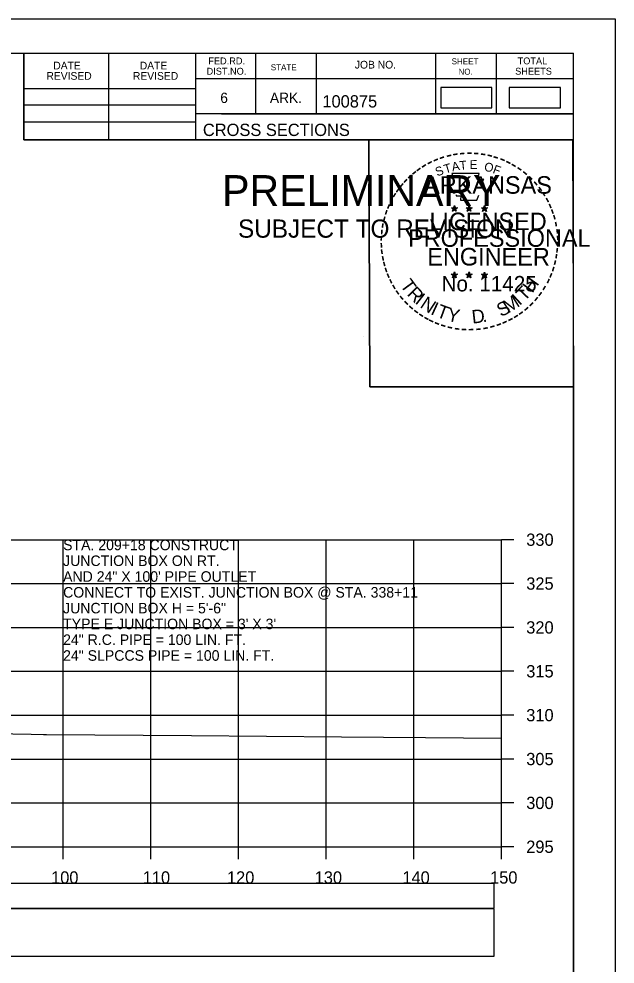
# Model space of a CAD drawing. Extents: x 1368122 to 1710785, y 373130 to 557566.
# Drawn here: x 1370117.2 to 1370185.2, y 374942.6 to 375050.4 of the extents above; entities that cross this region are included whole.
import ezdxf

# ---------------------------------------------------------------- set-up
doc = ezdxf.new("R2010")
doc.units = 0
for name, color, linetype in [('R_Axis', 7, 'Continuous'), ('R_Axis Annot', 7, 'Continuous'), ('R_Border', 7, 'Continuous'), ('R_Border PE', 7, 'Continuous'), ('R_Border Prem', 7, 'Continuous'), ('R_Drive', 7, 'Continuous'), ('R_Exist Surface', 7, 'Continuous'), ('R_Grid', 7, 'Continuous'), ('R_No Plot', 7, 'Continuous'), ('R_Water Annot', 7, 'Continuous')]:
    doc.layers.add(name, color=color, linetype=linetype)

msp = doc.modelspace()

# ---------------------------------------------------------------- linework, layer by layer
for points in [[(1369873.09, 374949), (1370171.39, 374949), (1370171.39, 374951.82), (1369873.09, 374951.82)], [(1369873.09, 374943.54), (1370171.39, 374943.54), (1370171.39, 374948.95), (1369873.09, 374948.95)]]:
    msp.add_lwpolyline(points, close=True)
at = {"layer": 'R_Axis'}
for p, q in [((1370172.24, 374956.01), (1370172.24, 374991.01)), ((1370173.64, 374991.01), (1370172.24, 374991.01)), ((1370173.64, 374986.01), (1370172.24, 374986.01)), ((1370173.64, 374981.01), (1370172.24, 374981.01)), ((1370173.64, 374976.01), (1370172.24, 374976.01)), ((1370173.64, 374971.01), (1370172.24, 374971.01)), ((1370173.64, 374966.01), (1370172.24, 374966.01)), ((1370173.64, 374961.01), (1370172.24, 374961.01)), ((1369872.24, 374956.01), (1370172.24, 374956.01)), ((1370122.24, 374954.61), (1370122.24, 374956.01)), ((1370132.24, 374954.61), (1370132.24, 374956.01)), ((1370142.24, 374954.61), (1370142.24, 374956.01)), ((1370152.24, 374954.61), (1370152.24, 374956.01)), ((1370162.24, 374954.61), (1370162.24, 374956.01)), ((1370172.24, 374954.61), (1370172.24, 374956.01)), ((1370173.64, 374956.01), (1370172.24, 374956.01))]:
    msp.add_line(p, q, dxfattribs=at)
at = {"layer": 'R_Border'}
for p, q in [((1369864.24, 375046.47), (1370180.42, 375046.47)), ((1370117.78, 375036.59), (1370117.78, 375046.47)), ((1370127.46, 375036.59), (1370127.46, 375046.47)), ((1370137.32, 375046.47), (1370137.32, 375036.59)), ((1370144.16, 375046.47), (1370144.16, 375039.53)), ((1370151.1, 375046.47), (1370151.1, 375039.53)), ((1370164.68, 375046.47), (1370164.68, 375039.53)), ((1370171.62, 375046.47), (1370171.62, 375039.53)), ((1370180.42, 374841.01), (1370180.42, 375046.47)), ((1370180.42, 375043.53), (1370137.32, 375043.53)), ((1370180.42, 375043.55), (1370180.42, 375043.55)), ((1370117.78, 375042.45), (1370137.32, 375042.45)), ((1370117.78, 375040.59), (1370137.32, 375040.59)), ((1370180.42, 375039.53), (1370137.32, 375039.53)), ((1370140.28, 375039.53), (1370180.42, 375039.53)), ((1370117.78, 375038.65), (1370137.32, 375038.65)), ((1370180.42, 375036.59), (1370117.78, 375036.59))]:
    msp.add_line(p, q, dxfattribs=at)
at = {"layer": 'R_Border PE'}
for p, q in [((1370166.51, 375028.85), (1370166.85, 375028.74)), ((1370166.51, 375028.85), (1370166.76, 375028.8)), ((1370166.51, 375028.85), (1370166.74, 375028.73)), ((1370166.64, 375028.44), (1370166.85, 375028.74)), ((1370166.64, 375028.44), (1370166.76, 375028.68)), ((1370166.64, 375028.44), (1370166.85, 375028.66)), ((1370166.85, 375029.1), (1370166.81, 375028.85)), ((1370166.85, 375028.74), (1370166.85, 375029.1)), ((1370166.85, 375029.1), (1370166.9, 375028.85)), ((1370167.2, 375028.85), (1370166.85, 375028.74)), ((1370167.07, 375028.44), (1370166.85, 375028.74)), ((1370167.07, 375028.44), (1370166.85, 375028.65)), ((1370167.2, 375028.85), (1370166.92, 375028.8)), ((1370167.07, 375028.44), (1370166.93, 375028.73)), ((1370167.2, 375028.85), (1370167, 375028.75)), ((1370168.18, 375028.85), (1370168.52, 375028.74)), ((1370168.18, 375028.85), (1370168.43, 375028.8)), ((1370168.18, 375028.85), (1370168.41, 375028.73)), ((1370168.31, 375028.44), (1370168.52, 375028.74)), ((1370168.31, 375028.44), (1370168.43, 375028.68)), ((1370168.31, 375028.44), (1370168.52, 375028.66)), ((1370168.52, 375029.1), (1370168.48, 375028.85)), ((1370168.52, 375028.74), (1370168.52, 375029.1)), ((1370168.52, 375029.1), (1370168.57, 375028.85)), ((1370168.87, 375028.85), (1370168.52, 375028.74)), ((1370168.74, 375028.44), (1370168.52, 375028.74)), ((1370168.74, 375028.44), (1370168.52, 375028.65)), ((1370168.87, 375028.85), (1370168.59, 375028.8)), ((1370168.74, 375028.44), (1370168.6, 375028.73)), ((1370168.87, 375028.85), (1370168.67, 375028.75)), ((1370169.94, 375028.84), (1370170.29, 375028.73)), ((1370169.94, 375028.84), (1370170.19, 375028.79)), ((1370169.94, 375028.84), (1370170.18, 375028.71)), ((1370170.07, 375028.43), (1370170.29, 375028.73)), ((1370170.07, 375028.43), (1370170.2, 375028.67)), ((1370170.07, 375028.43), (1370170.29, 375028.65)), ((1370170.29, 375029.09), (1370170.25, 375028.84)), ((1370170.29, 375028.73), (1370170.29, 375029.09)), ((1370170.29, 375029.09), (1370170.34, 375028.84)), ((1370170.64, 375028.84), (1370170.29, 375028.73)), ((1370170.5, 375028.43), (1370170.29, 375028.73)), ((1370170.5, 375028.43), (1370170.29, 375028.64)), ((1370170.64, 375028.84), (1370170.35, 375028.79)), ((1370170.5, 375028.43), (1370170.36, 375028.72)), ((1370170.64, 375028.84), (1370170.43, 375028.73)), ((1370166.5, 375021.28), (1370166.85, 375021.16)), ((1370166.5, 375021.28), (1370166.75, 375021.23)), ((1370166.5, 375021.28), (1370166.74, 375021.15)), ((1370166.63, 375020.87), (1370166.85, 375021.16)), ((1370166.63, 375020.87), (1370166.76, 375021.11)), ((1370166.63, 375020.87), (1370166.85, 375021.08)), ((1370166.85, 375021.53), (1370166.81, 375021.28)), ((1370166.85, 375021.16), (1370166.85, 375021.53)), ((1370166.85, 375021.53), (1370166.9, 375021.28)), ((1370167.2, 375021.28), (1370166.85, 375021.16)), ((1370167.06, 375020.87), (1370166.85, 375021.16)), ((1370167.06, 375020.87), (1370166.85, 375021.08)), ((1370167.2, 375021.28), (1370166.91, 375021.23)), ((1370167.06, 375020.87), (1370166.93, 375021.16)), ((1370167.2, 375021.28), (1370166.99, 375021.17)), ((1370168.17, 375021.28), (1370168.52, 375021.16)), ((1370168.17, 375021.28), (1370168.42, 375021.23)), ((1370168.17, 375021.28), (1370168.41, 375021.15)), ((1370168.3, 375020.87), (1370168.52, 375021.16)), ((1370168.3, 375020.87), (1370168.43, 375021.11)), ((1370168.3, 375020.87), (1370168.52, 375021.08)), ((1370168.52, 375021.53), (1370168.48, 375021.28)), ((1370168.52, 375021.16), (1370168.52, 375021.53)), ((1370168.52, 375021.53), (1370168.57, 375021.28)), ((1370168.87, 375021.28), (1370168.52, 375021.16)), ((1370168.73, 375020.87), (1370168.52, 375021.16)), ((1370168.73, 375020.87), (1370168.52, 375021.08)), ((1370168.87, 375021.28), (1370168.58, 375021.23)), ((1370168.73, 375020.87), (1370168.6, 375021.16)), ((1370168.87, 375021.28), (1370168.66, 375021.17)), ((1370169.94, 375021.27), (1370170.29, 375021.15)), ((1370169.94, 375021.27), (1370170.19, 375021.22)), ((1370169.94, 375021.27), (1370170.17, 375021.14)), ((1370170.07, 375020.86), (1370170.29, 375021.15)), ((1370170.07, 375020.86), (1370170.2, 375021.1)), ((1370170.07, 375020.86), (1370170.28, 375021.07)), ((1370170.29, 375021.52), (1370170.25, 375021.27)), ((1370170.5, 375020.86), (1370170.28, 375021.07)), ((1370170.29, 375021.15), (1370170.29, 375021.52)), ((1370170.29, 375021.52), (1370170.34, 375021.27)), ((1370170.63, 375021.27), (1370170.29, 375021.15)), ((1370170.5, 375020.86), (1370170.29, 375021.15)), ((1370170.63, 375021.27), (1370170.35, 375021.22)), ((1370170.5, 375020.86), (1370170.36, 375021.15)), ((1370170.63, 375021.27), (1370170.43, 375021.16))]:
    msp.add_line(p, q, dxfattribs=at)
for points in [[(1370166.55, 375032.73), (1370166.82, 375031.9)], [(1370170.06, 375031.8), (1370170.2, 375032.09), (1370169.51, 375032.06), (1370169.66, 375032.73), (1370166.55, 375032.73)], [(1370167.04, 375030.3), (1370167.04, 375030.22), (1370167.6, 375030.2), (1370167.55, 375029.72), (1370169.42, 375029.72), (1370169.62, 375030.26)], [(1370166.85, 375029.1), (1370167.07, 375028.44), (1370166.51, 375028.85), (1370167.2, 375028.85), (1370166.64, 375028.44), (1370166.85, 375029.1)], [(1370168.52, 375029.1), (1370168.74, 375028.44), (1370168.18, 375028.85), (1370168.87, 375028.85), (1370168.31, 375028.44), (1370168.52, 375029.1)], [(1370170.29, 375029.09), (1370170.5, 375028.43), (1370169.94, 375028.84), (1370170.64, 375028.84), (1370170.07, 375028.43), (1370170.29, 375029.09)], [(1370166.85, 375021.53), (1370167.06, 375020.87), (1370166.5, 375021.28), (1370167.2, 375021.28), (1370166.63, 375020.87), (1370166.85, 375021.53)], [(1370168.52, 375021.53), (1370168.73, 375020.87), (1370168.17, 375021.28), (1370168.87, 375021.28), (1370168.3, 375020.87), (1370168.52, 375021.53)], [(1370170.29, 375021.52), (1370170.5, 375020.86), (1370169.94, 375021.27), (1370170.63, 375021.27), (1370170.07, 375020.86), (1370170.29, 375021.52)]]:
    msp.add_lwpolyline(points, dxfattribs=at)
for centre, radius in [((1370166.85, 375028.74), 0.172), ((1370166.85, 375028.74), 0.145), ((1370166.85, 375028.74), 0.116), ((1370166.85, 375028.74), 0.0991), ((1370166.85, 375028.74), 0.0747), ((1370166.85, 375028.74), 0.0495), ((1370166.85, 375028.74), 0.0296), ((1370168.52, 375028.74), 0.172), ((1370168.52, 375028.74), 0.145), ((1370168.52, 375028.74), 0.116), ((1370168.52, 375028.74), 0.0991), ((1370168.52, 375028.74), 0.0747), ((1370168.52, 375028.74), 0.0495), ((1370168.52, 375028.74), 0.0296), ((1370170.29, 375028.72), 0.172), ((1370170.29, 375028.72), 0.145), ((1370170.29, 375028.72), 0.116), ((1370170.29, 375028.72), 0.0991), ((1370170.29, 375028.72), 0.0747), ((1370170.29, 375028.72), 0.0495), ((1370170.29, 375028.72), 0.0296), ((1370166.85, 375021.16), 0.172), ((1370166.85, 375021.16), 0.145), ((1370166.85, 375021.16), 0.116), ((1370166.85, 375021.16), 0.0991), ((1370166.85, 375021.16), 0.0747), ((1370166.85, 375021.16), 0.0495), ((1370166.85, 375021.16), 0.0296), ((1370168.52, 375021.16), 0.172), ((1370168.52, 375021.16), 0.145), ((1370168.52, 375021.16), 0.116), ((1370168.52, 375021.16), 0.0991), ((1370168.52, 375021.16), 0.0747), ((1370168.52, 375021.16), 0.0495), ((1370168.52, 375021.16), 0.0296), ((1370170.29, 375021.15), 0.172), ((1370170.29, 375021.15), 0.145), ((1370170.29, 375021.15), 0.116), ((1370170.29, 375021.15), 0.0991), ((1370170.29, 375021.15), 0.0747), ((1370170.29, 375021.15), 0.0495), ((1370170.29, 375021.15), 0.0296)]:
    msp.add_circle(centre, radius, dxfattribs=at)
at = {"layer": 'R_Drive'}
for points in [[(1370165.29, 375040.25), (1370171.13, 375040.25), (1370171.13, 375042.56), (1370165.29, 375042.56)], [(1370173.1, 375040.25), (1370178.94, 375040.25), (1370178.94, 375042.56), (1370173.1, 375042.56)]]:
    msp.add_lwpolyline(points, close=True, dxfattribs=at)
at = {"layer": 'R_Exist Surface'}
msp.add_lwpolyline([(1370066.84, 374970.53), (1370074.01, 374970.13), (1370083.2, 374969.84), (1370085.11, 374969.76), (1370089.62, 374969.69), (1370092.69, 374969.65), (1370093.81, 374969.62), (1370095.6, 374969.58), (1370103.81, 374969.35), (1370113.73, 374969.01), (1370116.49, 374968.89), (1370118.6, 374968.84), (1370120.02, 374968.82), (1370120.34, 374968.81), (1370136.86, 374968.68), (1370153.98, 374968.54), (1370163.55, 374968.47), (1370172.24, 374968.4)], dxfattribs=at)
at = {"layer": 'R_Grid'}
for p, q in [((1369872.24, 374991.01), (1370172.24, 374991.01)), ((1370122.24, 374956.01), (1370122.24, 374991.01)), ((1370132.24, 374956.01), (1370132.24, 374991.01)), ((1370142.24, 374956.01), (1370142.24, 374991.01)), ((1370152.24, 374956.01), (1370152.24, 374991.01)), ((1370162.24, 374956.01), (1370162.24, 374991.01)), ((1370172.24, 374956.01), (1370172.24, 374991.01)), ((1369872.24, 374986.01), (1370172.24, 374986.01)), ((1369872.24, 374981.01), (1370172.24, 374981.01)), ((1369872.24, 374976.01), (1370172.24, 374976.01)), ((1369872.24, 374971.01), (1370172.24, 374971.01)), ((1369872.24, 374966.01), (1370172.24, 374966.01)), ((1369872.24, 374961.01), (1370172.24, 374961.01)), ((1369872.24, 374956.01), (1370172.24, 374956.01))]:
    msp.add_line(p, q, dxfattribs=at)
at = {"layer": 'R_No Plot'}
for p, q in [((1369851.84, 375050.37), (1370185.17, 375050.37)), ((1370156.45, 375014.14), (1370156.45, 375014.14))]:
    msp.add_line(p, q, dxfattribs=at)
for points in [[(1369851.83, 375050.37), (1370185.17, 375050.37), (1370185.17, 374837.03), (1369851.83, 374837.03)], [(1370098.16, 375046.47), (1370117.78, 375046.47), (1370117.78, 375036.59), (1370133.89, 375036.59), (1370157.09, 375036.59), (1370157.21, 375008.44), (1370180.42, 375008.44), (1370180.42, 374841.01), (1369864.24, 374841.01), (1369864.24, 375046.47)], [(1370157.09, 375036.59), (1370180.3, 375036.59), (1370180.42, 375008.44), (1370157.21, 375008.44)]]:
    msp.add_lwpolyline(points, close=True, dxfattribs=at)

# ---------------------------------------------------------------- texts
at = {"layer": 'R_Axis Annot'}
for s, p in [('330', (1370175.04, 374990.31)), ('325', (1370175.04, 374985.31)), ('320', (1370175.04, 374980.31)), ('315', (1370175.04, 374975.31)), ('310', (1370175.04, 374970.31)), ('305', (1370175.04, 374965.31)), ('300', (1370175.04, 374960.31)), ('295', (1370175.04, 374955.31)), ('100', (1370120.87, 374951.81)), ('110', (1370131.32, 374951.81)), ('120', (1370140.92, 374951.81)), ('130', (1370150.92, 374951.81)), ('140', (1370160.92, 374951.81)), ('150', (1370170.92, 374951.81))]:
    msp.add_text(s, height=1.4, dxfattribs=at).set_placement(p)
at = {"layer": 'R_Border'}
for s, height, p in [('FED.RD.', 0.782, (1370138.8, 375045.19)), ('JOB NO.', 0.879, (1370155.5, 375044.71)), ('SHEET', 0.684, (1370166.54, 375045.19)), ('TOTAL', 0.782, (1370174.06, 375045.19)), ('DATE', 0.879, (1370121.12, 375044.61)), ('DATE', 0.879, (1370130.98, 375044.61)), ('DIST.NO.', 0.782, (1370138.6, 375044.01)), ('STATE', 0.684, (1370145.92, 375044.51)), ('NO.', 0.684, (1370167.32, 375044.01)), ('SHEETS', 0.782, (1370173.78, 375044.01)), ('REVISED', 0.879, (1370120.34, 375043.43)), ('REVISED', 0.879, (1370130.2, 375043.43)), ('6', 1.17, (1370140.16, 375040.79)), ('ARK.', 1.172, (1370145.82, 375040.79)), ('100875', 1.4, (1370151.8, 375040.27)), ('CROSS SECTIONS', 1.4, (1370138.18, 375037.02))]:
    msp.add_text(s, height=height, rotation=360, dxfattribs=at).set_placement(p)
at = {"layer": 'R_Border PE'}
for s, height, rotation, p in [('-', 1.6, 13.6301, (1370166.04, 375034.09)), ('-', 1.6, 10.2193, (1370166.72, 375034.26)), ('-', 1.6, 5.8968, (1370167.45, 375034.37)), ('-', 1.6, 0.1862, (1370168.22, 375034.44)), ('-', 1.6, 357.743, (1370168.95, 375034.43)), ('-', 1.6, 352.1617, (1370169.69, 375034.37)), ('-', 1.6, 347.2049, (1370170.41, 375034.26)), ('-', 1.6, 34.0636, (1370163.43, 375032.9)), ('-', 1.6, 28.7918, (1370164.03, 375033.27)), ('-', 1.6, 24.3072, (1370164.66, 375033.58)), ('-', 1.6, 19.1761, (1370165.29, 375033.85)), ('T', 1, 16.4036, (1370165.82, 375032.74)), ('A', 1, 11.2132, (1370166.64, 375032.99)), ('T', 1, 6.0228, (1370167.49, 375033.15)), ('E', 1, 0.8323, (1370168.6, 375033.26)), ('O', 1, 350.4515, (1370170.2, 375033.05)), ('F', 1, 340.0707, (1370171.15, 375032.82)), ('-', 1.6, 342.3362, (1370171.04, 375034.1)), ('-', 1.6, 337.8551, (1370171.78, 375033.88)), ('-', 1.6, 334.1211, (1370172.41, 375033.61)), ('-', 1.6, 329.6409, (1370172.99, 375033.32)), ('-', 1.6, 42.9622, (1370161.94, 375031.71)), ('-', 1.6, 38.9507, (1370162.38, 375032.12)), ('-', 1.6, 36.2317, (1370162.85, 375032.5)), ('S', 1, 21.594, (1370164.9, 375032.4)), ('-', 1.6, 325.8627, (1370173.63, 375032.96)), ('-', 1.6, 320.5297, (1370174.24, 375032.54)), ('-', 1.6, 50.6142, (1370161.09, 375030.74)), ('-', 1.6, 48.423, (1370161.5, 375031.23)), ('ARKANSAS', 2, 360, (1370163.4, 375030.44)), ('-', 1.6, 315.5786, (1370174.84, 375032.05)), ('-', 1.6, 309.8797, (1370175.41, 375031.5)), ('-', 1.6, 58.0706, (1370160.35, 375029.65)), ('-', 1.6, 54.2325, (1370160.68, 375030.18)), ('-', 1.6, 306.6522, (1370175.94, 375030.9)), ('-', 1.4, 303.6753, (1370176.42, 375030.33)), ('-', 1.6, 62.8713, (1370160.04, 375029.04)), ('-', 1.6, 299.6684, (1370176.74, 375029.72)), ('-', 1.6, 72.3945, (1370159.56, 375027.79)), ('-', 1.6, 67.7743, (1370159.78, 375028.42)), ('DWB', 0.01, 360, (1370166.84, 375028.73)), ('DWB', 0.01, 360, (1370168.51, 375028.73)), ('DWB', 0.01, 360, (1370170.28, 375028.72)), ('-', 1.6, 294.6628, (1370177.06, 375029.11)), ('-', 1.6, 290.5728, (1370177.32, 375028.53)), ('-', 1.6, 75.461, (1370159.37, 375027.08)), ('LICENSED', 2, 360, (1370164, 375026.29)), ('-', 1.6, 285.1233, (1370177.56, 375027.95)), ('-', 1.6, 85.1863, (1370159.16, 375025.68)), ('-', 1.6, 81.2013, (1370159.23, 375026.37)), ('PROFESSIONAL', 2, 360, (1370161.57, 375024.39)), ('-', 1.6, 280.5493, (1370177.76, 375027.21)), ('-', 1.6, 276.5962, (1370177.92, 375026.44)), ('-', 1.6, 89.0622, (1370159.13, 375024.98)), ('-', 1.6, 274.3301, (1370177.98, 375025.72)), ('-', 1.6, 94.1959, (1370159.17, 375024.25)), ('-', 1.6, 98.9479, (1370159.24, 375023.58)), ('ENGINEER', 2, 360, (1370163.76, 375022.26)), ('-', 1.6, 263.5172, (1370177.99, 375024.42)), ('-', 1.6, 269.9407, (1370178.01, 375025.09)), ('-', 1.6, 101.7149, (1370159.38, 375022.85)), ('-', 1.6, 260.9953, (1370177.92, 375023.77)), ('-', 1.6, 105.4578, (1370159.54, 375022.26)), ('-', 1.6, 109.0874, (1370159.75, 375021.62)), ('-', 1.6, 252.8681, (1370177.63, 375022.37)), ('-', 1.6, 255.7626, (1370177.81, 375023.09)), ('-', 1.6, 114.0643, (1370160.01, 375021.03)), ('T', 1.54, 306.0406, (1370160.61, 375020)), ('No. 11425', 1.757, 360, (1370165.39, 375019.31)), ('DWB', 0.01, 360, (1370166.84, 375021.16)), ('DWB', 0.01, 360, (1370168.51, 375021.16)), ('DWB', 0.01, 360, (1370170.27, 375021.15)), ('H', 1.54, 54.6088, (1370175.73, 375019.04)), ('-', 1.6, 247.8887, (1370177.41, 375021.7)), ('-', 1.6, 115.7289, (1370160.31, 375020.41)), ('-', 1.6, 120.4471, (1370160.67, 375019.82)), ('R', 1.54, 314.005, (1370161.37, 375018.95)), ('T', 1.54, 46.6444, (1370174.84, 375018.1)), ('-', 1.6, 239.0712, (1370176.75, 375020.32)), ('-', 1.6, 244.6197, (1370177.15, 375021.07)), ('-', 1.6, 125.8934, (1370161.07, 375019.26)), ('-', 1.6, 130.7181, (1370161.53, 375018.71)), ('I', 1.54, 321.9694, (1370162.27, 375018.02)), ('N', 1.54, 326.5002, (1370162.84, 375017.55)), ('M', 1.54, 32.6563, (1370172.99, 375016.77)), ('I', 1.54, 42.1136, (1370174.28, 375017.62)), ('-', 1.6, 231.2538, (1370175.92, 375019.1)), ('-', 1.6, 233.8452, (1370176.35, 375019.66)), ('-', 1.6, 134.2238, (1370162.05, 375018.17)), ('-', 1.6, 138.9338, (1370162.58, 375017.7)), ('I', 1.54, 335.3603, (1370164.05, 375016.76)), ('T', 1.54, 339.8912, (1370164.71, 375016.44)), ('S', 1.54, 26.9312, (1370172.16, 375016.36)), ('-', 1.6, 221.0851, (1370174.92, 375018.02)), ('-', 1.6, 225.7653, (1370175.44, 375018.53)), ('-', 1.6, 144.6463, (1370163.13, 375017.3)), ('-', 1.6, 148.0898, (1370163.69, 375016.93)), ('Y', 1.54, 347.8556, (1370165.93, 375015.99)), ('D', 1.54, 6.3969, (1370168.91, 375015.63)), ('-', 1.6, 212.2491, (1370173.84, 375017.17)), ('-', 1.6, 215.7363, (1370174.37, 375017.55)), ('-', 1.6, 151.5704, (1370164.27, 375016.6)), ('-', 1.6, 154.6002, (1370164.79, 375016.35)), ('-', 1.6, 158.5612, (1370165.42, 375016.1)), ('-', 1.6, 162.7983, (1370166.1, 375015.89)), ('.', 1.54, 13.7642, (1370170.1, 375015.76)), ('-', 1.6, 195.4743, (1370171.36, 375015.99)), ('-', 1.6, 200.7184, (1370172.03, 375016.23)), ('-', 1.6, 204.2516, (1370172.65, 375016.5)), ('-', 1.6, 207.3568, (1370173.28, 375016.82)), ('-', 1.6, 167.5555, (1370166.82, 375015.72)), ('-', 1.6, 173.1155, (1370167.59, 375015.61)), ('-', 1.6, 176.5183, (1370168.34, 375015.56)), ('-', 1.6, 181.5918, (1370169.08, 375015.58)), ('-', 1.6, 185.8167, (1370169.89, 375015.65)), ('-', 1.6, 191.2858, (1370170.63, 375015.79))]:
    msp.add_text(s, height=height, rotation=rotation, dxfattribs=at).set_placement(p)
at = {"layer": 'R_Border Prem'}
for s, height, p in [('PRELIMINARY', 3.5, (1370140.37, 375029.06)), ('DWB', 0.01, (1370141.12, 375030.91)), ('SUBJECT TO REVISION', 2.0751, (1370142.18, 375025.43))]:
    msp.add_text(s, height=height, rotation=360, dxfattribs=at).set_placement(p)
at = {"layer": 'R_Water Annot'}
for s, p in [('STA. 209+18 CONSTRUCT', (1370122.24, 374989.81)), ('JUNCTION BOX ON RT.', (1370122.24, 374988.01)), ('AND 24" X 100\' PIPE OUTLET', (1370122.24, 374986.21)), ('CONNECT TO EXIST. JUNCTION BOX @ STA. 338+11', (1370122.24, 374984.41)), ('JUNCTION BOX H = 5\'-6"', (1370122.24, 374982.61)), ("TYPE E JUNCTION BOX = 3' X 3'", (1370122.24, 374980.81)), ('24" R.C. PIPE = 100 LIN. FT.', (1370122.24, 374979.01)), ('24" SLPCCS PIPE = 100 LIN. FT.', (1370122.24, 374977.21))]:
    msp.add_text(s, height=1.2, dxfattribs=at).set_placement(p)

doc.saveas('drawing.dxf')
